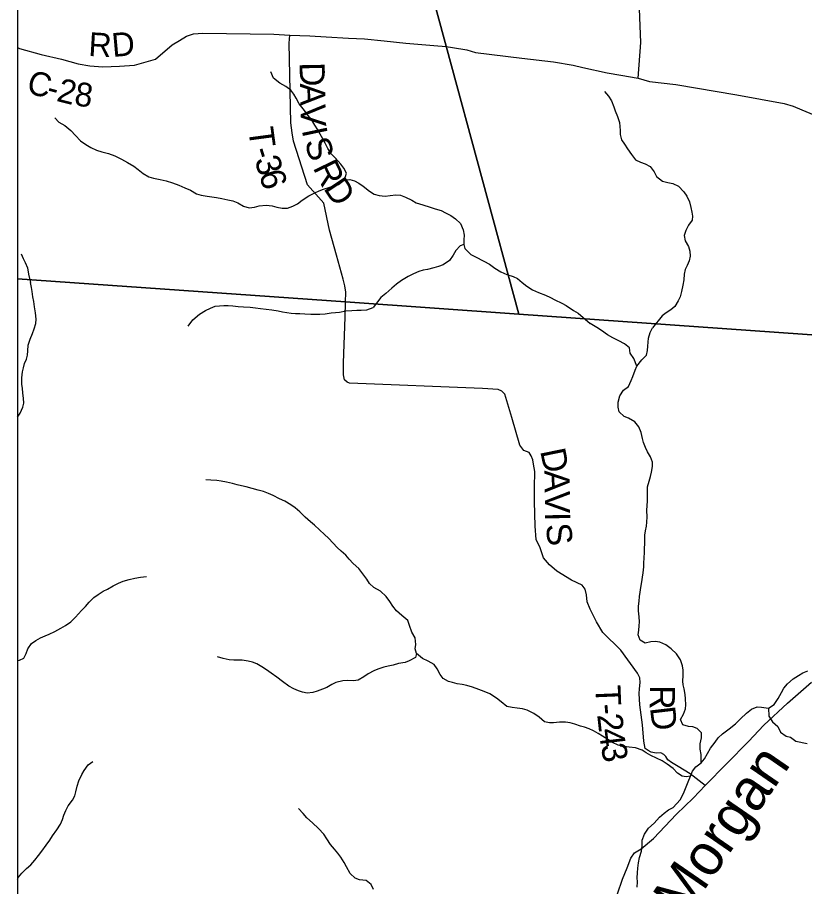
# Model space of a CAD drawing. Extents: x -139 to 835, y 0 to 440.
# Drawn here: x 67.6 to 127.4, y 290.4 to 356.4 of the extents above; entities that cross this region are included whole.
import ezdxf

# ---------------------------------------------------------------- set-up
doc = ezdxf.new("R2010")
doc.units = 0
for name, color, linetype in [('Default', 7, 'Continuous'), ('GM_X_County_Road', 7, 'Continuous'), ('GM_X_County_Road_Text', 7, 'Continuous'), ('GM_X_County_Text', 7, 'Continuous'), ('GM_X_Minor_River', 7, 'Continuous'), ('GM_X_Minor_River_Text', 7, 'Continuous'), ('GM_X_Township_Road', 7, 'Continuous'), ('GM_X_Township_Road_Text', 7, 'Continuous'), ('SH_Cut_Line', 7, 'Continuous')]:
    doc.layers.add(name, color=color, linetype=linetype)

msp = doc.modelspace()

# ---------------------------------------------------------------- linework, layer by layer
at = {"layer": 'Default'}
msp.add_lwpolyline([(122.213, 350.484), (122.213, 350.484), (122.213, 350.484), (122.213, 350.484)], close=True, dxfattribs=at)
at = {"layer": 'GM_X_County_Road'}
for points in [[(67.578, 354.075), (67.744, 354.001), (69.374, 353.566), (70.924, 353.205), (72.198, 352.834), (73.073, 352.682), (74.077, 352.622), (75.337, 352.662), (76.469, 352.753), (78.065, 353.205), (79.345, 354.278), (79.89, 354.624), (80.429, 354.959), (80.946, 355.122), (81.654, 355.177), (87.067, 355.109), (88.262, 355.036), (89.792, 354.973), (91.035, 354.9), (92.738, 354.8), (93.952, 354.741), (95.425, 354.596), (97.089, 354.415), (99.212, 354.251), (100.152, 354.161), (100.624, 354.086)], [(100.624, 354.086), (101.703, 353.916), (102.381, 353.715), (105.89, 353.277), (108.3, 352.994), (109.782, 352.747), (110.527, 352.58), (112.371, 352.161), (113.415, 351.988), (114.73, 351.757), (115.597, 351.513), (117.577, 351.268), (122.213, 350.484), (125.805, 349.823), (126.493, 349.639), (127.165, 349.341), (128.555, 348.774)], [(113.147, 289.815), (113.54, 290.92), (113.892, 291.773), (114.179, 292.518), (114.437, 292.913), (114.948, 293.234), (115.882, 294.02), (117.639, 295.859), (118.895, 297.076), (119.378, 297.567), (119.818, 298.043), (123.113, 301.386), (124.268, 302.604), (126.061, 304.297), (127.891, 305.87)]]:
    msp.add_lwpolyline(points, dxfattribs=at)
at = {"layer": 'GM_X_County_Text'}
for points in [[(87.298, 401.486), (67.578, 401.486), (67.578, 336.518), (92.493, 334.759), (105.67, 333.828), (100.145, 354.177), (90.116, 391.109)], [(205.139, 401.486), (87.298, 401.486), (90.116, 391.109), (100.145, 354.177), (105.67, 333.828), (158.444, 330.1), (160.688, 329.921), (171.559, 329.033), (172.321, 330.669), (184.767, 357.384), (185.383, 358.364), (185.729, 359.048), (185.902, 359.821), (186.018, 360.334), (186.292, 360.95), (186.616, 361.275), (187.014, 361.689), (203.078, 396.689), (203.294, 397.153), (203.246, 397.371), (203.278, 397.973), (203.623, 399.152)]]:
    msp.add_lwpolyline(points, close=True, dxfattribs=at)
msp.add_lwpolyline([(164.238, 274.594), (166.338, 293.196), (166.41, 293.836), (158.512, 319.627), (160.688, 329.921), (158.444, 330.1), (105.67, 333.828), (92.493, 334.759), (67.578, 336.518), (67.578, 185.387)], dxfattribs=at)
at = {"layer": 'GM_X_Minor_River'}
for points in [[(92.421, 344.046), (92.566, 344.538), (92.368, 344.926), (92.156, 345.23), (91.719, 345.705), (91.406, 346.01), (91.145, 346.423), (90.947, 346.81), (90.786, 347.15), (90.563, 347.514), (90.389, 347.829), (90.178, 348.181), (89.904, 348.606), (89.63, 348.959), (89.394, 349.311), (88.981, 349.798), (88.759, 350.234), (88.572, 350.538), (88.348, 350.842), (87.971, 351.123), (87.506, 351.382), (87.041, 351.761), (86.819, 352.245)], [(112.169, 350.733), (112.469, 350.38), (112.706, 350.028), (112.89, 349.592), (112.975, 349.289), (113.16, 348.853), (113.306, 348.381), (113.341, 348.08), (113.362, 347.778), (113.371, 347.476), (113.455, 347.066), (113.679, 346.75), (113.928, 346.397), (114.214, 345.948), (114.526, 345.547), (114.904, 345.374), (115.27, 345.249), (115.647, 345.04), (115.947, 344.639), (116.132, 344.287), (116.571, 343.933), (116.988, 343.844), (117.367, 343.755), (117.783, 343.557), (118.196, 343.131), (118.433, 342.803), (118.63, 342.354), (118.726, 341.931), (118.798, 341.581), (118.845, 341.267), (118.816, 340.966), (118.558, 340.583), (118.35, 340.176), (118.218, 339.803), (118.302, 339.405), (118.55, 338.968), (118.647, 338.617), (118.668, 338.243), (118.6, 337.882), (118.444, 337.535), (118.301, 337.223), (118.233, 336.862), (118.19, 336.44), (118.121, 336.031), (118.027, 335.562), (117.908, 335.154), (117.764, 334.842), (117.518, 334.411), (117.199, 334.173), (116.866, 333.936), (116.547, 333.71), (115.807, 332.785)], [(70.417, 348.751), (70.717, 348.41), (71.183, 348.164), (71.634, 347.773), (71.997, 347.395), (72.372, 347.005), (72.774, 346.724), (73.152, 346.502), (73.58, 346.293), (73.984, 346.168), (74.502, 346.029), (74.981, 345.855), (75.498, 345.608), (75.951, 345.362), (76.416, 345.068), (76.743, 344.823), (77.119, 344.517), (77.56, 344.271), (77.926, 344.171), (78.431, 344.069), (78.874, 343.955), (79.353, 343.805), (79.845, 343.631), (80.299, 343.433), (80.715, 343.248), (81.18, 342.965), (81.534, 342.865), (81.989, 342.788), (82.343, 342.735), (82.71, 342.695), (83.102, 342.63), (83.57, 342.529), (83.936, 342.452), (84.327, 342.291), (84.742, 342.033), (85.184, 341.92), (85.578, 341.964), (85.946, 342.068), (86.467, 342.123), (86.922, 342.069), (87.288, 341.969), (87.68, 341.88), (88.098, 341.876), (88.493, 342.028), (88.85, 342.217), (89.208, 342.502), (89.707, 342.822), (90.166, 343.058), (90.497, 343.199), (90.828, 343.316), (91.298, 343.467), (91.642, 343.572), (91.96, 343.677), (92.421, 344.046), (92.839, 344.065), (93.18, 343.953), (93.507, 343.792), (93.834, 343.548), (94.311, 343.181), (94.688, 342.959), (95.067, 342.847), (95.523, 342.805), (95.891, 342.837), (96.309, 342.893), (96.676, 342.865), (97.055, 342.728), (97.546, 342.494), (97.873, 342.297), (98.378, 342.147), (98.921, 341.948), (99.299, 341.835), (99.754, 341.697), (100.094, 341.537), (100.497, 341.327), (100.862, 341.082), (101.237, 340.728), (101.447, 340.232), (101.505, 339.845), (101.488, 339.472), (101.496, 339.134), (101.569, 338.82), (102.019, 338.369), (102.372, 338.196), (103.001, 337.852), (103.442, 337.618), (103.844, 337.324), (104.309, 337.041), (104.763, 336.844), (105.23, 336.694), (105.57, 336.533), (105.921, 336.228), (106.272, 335.947), (106.713, 335.689), (107.154, 335.491), (107.683, 335.268), (108.074, 335.107), (108.401, 334.922), (108.918, 334.663), (109.27, 334.479), (109.823, 334.123), (110.163, 333.902)], [(101.496, 339.134), (101.204, 339.029), (100.87, 338.671), (100.675, 338.312), (100.391, 337.905), (99.919, 337.585), (99.562, 337.444), (99.206, 337.352), (98.736, 337.236), (98.406, 337.168), (98.062, 337.075), (97.667, 336.887), (97.247, 336.686), (96.762, 336.402), (96.378, 336.105), (96.007, 335.82), (95.571, 335.415), (95.187, 335.094), (94.601, 334.333)], [(67.87, 338.412), (68.017, 338.061), (68.166, 337.746), (68.338, 337.346), (68.421, 336.863), (68.568, 336.233)], [(67.578, 326.019), (67.786, 326.304), (68.002, 326.763), (68.066, 327.065), (68.041, 327.463), (68.003, 327.838), (67.965, 328.2), (67.927, 328.502), (67.914, 329.009), (67.978, 329.456), (68.041, 329.758), (68.118, 330.096), (68.271, 330.411), (68.334, 330.713), (68.36, 331.051), (68.398, 331.473), (68.551, 331.932), (68.729, 332.355), (68.856, 332.718), (68.971, 333.128), (68.996, 333.454), (68.958, 333.925), (68.882, 334.384), (68.819, 334.795), (68.756, 335.145), (68.692, 335.544), (68.642, 335.846), (68.568, 336.233)], [(80.537, 332.922), (80.906, 333.393), (81.415, 333.84), (81.872, 334.118), (82.241, 334.299), (82.597, 334.432), (82.927, 334.468), (83.27, 334.492), (83.588, 334.492), (83.944, 334.456), (84.338, 334.42), (84.758, 334.395), (85.253, 334.371), (85.673, 334.323), (86.054, 334.262), (86.461, 334.202), (86.893, 334.154), (87.376, 334.081), (87.719, 334.021), (88.037, 333.948), (88.367, 333.9), (88.71, 333.888), (89.041, 333.876), (89.422, 333.851), (89.854, 333.839), (90.553, 333.839), (90.96, 333.863), (91.405, 333.924), (91.735, 333.96), (92.053, 333.996), (92.536, 334.081), (92.968, 334.117), (93.35, 334.129), (93.68, 334.129), (94.125, 334.165), (94.601, 334.333)], [(110.163, 333.902), (111.071, 333.131)], [(114.637, 329.876), (114.396, 330.467), (114.116, 330.878), (114.066, 331.265), (113.685, 331.591), (113.253, 331.82), (112.808, 332.038), (112.389, 332.255), (111.931, 332.581), (111.575, 332.811), (111.071, 333.131)], [(119.508, 299.745), (119.516, 300.377), (119.44, 300.788), (119.44, 301.198), (119.542, 301.657), (119.542, 302.032), (119.199, 302.37), (118.881, 302.479), (118.551, 302.515), (118.119, 302.648), (117.954, 303.035), (118.17, 303.457), (118.31, 303.856), (118.336, 304.17), (118.31, 304.605), (118.285, 304.955), (118.209, 305.366), (118.146, 305.668), (118.12, 305.97), (118.146, 306.381), (118.146, 306.792), (118.096, 307.13), (117.931, 307.577), (117.651, 308.024), (117.232, 308.422), (116.838, 308.712), (116.381, 308.918), (116.025, 308.966), (115.694, 308.942), (115.262, 308.845), (114.881, 309.063), (114.729, 309.486), (114.78, 309.824), (114.793, 310.162), (114.818, 310.476), (114.793, 310.85), (114.742, 311.31), (114.755, 311.66), (114.793, 312.034), (114.819, 312.385), (114.87, 312.711), (114.934, 313.061), (115.01, 313.508), (115.061, 313.846), (115.1, 314.197), (115.151, 314.631), (115.164, 314.933), (115.189, 315.32), (115.202, 315.719), (115.215, 316.045), (115.228, 316.419), (115.228, 316.745), (115.241, 317.059), (115.292, 317.386), (115.356, 317.724), (115.394, 318.026), (115.407, 318.436), (115.382, 318.92), (115.42, 319.306), (115.445, 319.62), (115.446, 319.958), (115.433, 320.405), (115.446, 320.707), (115.561, 321.154), (115.662, 321.492), (115.739, 321.843), (115.815, 322.253), (115.828, 322.58), (115.663, 322.99), (115.435, 323.389), (115.282, 323.715), (115.143, 324.089), (115.067, 324.392), (114.952, 324.851), (114.787, 325.273), (114.47, 325.66), (113.987, 325.926), (113.657, 326.071), (113.288, 326.421), (113.212, 326.759), (113.212, 327.158), (113.34, 327.641), (113.619, 328.052), (114.001, 328.341), (114.204, 328.8), (114.319, 329.102), (114.497, 329.574), (114.637, 329.876), (114.993, 330.359), (115.362, 330.709), (115.438, 331.071), (115.464, 331.397), (115.49, 331.711), (115.515, 332.013), (115.63, 332.448), (115.807, 332.785)], [(82.718, 321.193), (82.273, 321.229), (81.892, 321.241)], [(118.69, 298.737), (118.383, 298.698), (118.066, 298.734), (117.71, 298.976), (117.392, 299.326), (116.935, 299.652), (116.541, 299.918), (116.109, 300.099), (115.69, 300.305), (115.347, 300.51), (115.029, 300.715), (114.533, 300.885), (114.051, 300.957), (113.644, 301.005), (113.212, 301.102), (112.767, 301.308), (112.424, 301.537), (112.017, 301.791), (111.7, 301.972), (111.344, 302.177), (111.001, 302.334), (110.658, 302.467), (110.34, 302.552), (109.921, 302.685), (109.565, 302.781), (109.209, 302.842), (108.764, 302.842), (108.307, 302.794), (107.989, 302.794), (107.62, 302.878), (107.214, 303.229), (106.807, 303.506), (106.286, 303.748), (105.943, 303.857), (105.536, 303.917), (105.155, 303.954), (104.748, 304.038), (104.329, 304.376), (103.973, 304.666), (103.465, 304.992), (103.033, 305.174), (102.627, 305.319), (102.156, 305.512), (101.724, 305.633), (101.356, 305.693), (100.987, 305.766), (100.631, 305.85), (100.314, 305.935), (99.907, 306.164), (99.678, 306.466), (99.463, 306.901), (99.221, 307.215), (98.777, 307.481), (98.357, 307.687), (97.9, 308.049), (97.798, 308.424), (97.849, 308.75), (97.786, 309.257), (97.532, 309.68), (97.367, 310.187), (97.227, 310.562), (96.783, 310.936), (96.376, 311.299), (96.084, 311.649), (95.868, 312.011), (95.589, 312.386), (95.157, 312.785), (94.649, 313.075), (94.318, 313.377), (94.115, 313.715), (93.747, 314.21), (93.505, 314.512), (93.073, 314.887), (92.781, 315.213), (92.515, 315.539), (92.172, 315.829), (91.854, 316.119), (91.562, 316.445), (91.206, 316.807), (90.901, 317.109), (90.52, 317.448), (90.152, 317.798), (89.834, 318.064), (89.427, 318.426), (89.034, 318.825), (88.665, 319.127), (88.335, 319.344), (87.89, 319.622), (87.496, 319.816), (87.013, 320.057), (86.658, 320.214), (86.276, 320.359), (85.857, 320.468), (85.399, 320.589), (84.955, 320.722), (84.599, 320.806), (84.281, 320.879), (83.925, 320.975), (83.455, 321.072), (83.048, 321.145), (82.718, 321.193)], [(67.578, 307.54), (67.739, 307.544), (68.057, 307.701), (68.248, 308.052), (68.362, 308.402), (68.642, 308.813), (68.985, 309.054), (69.329, 309.247), (69.685, 309.404), (70.002, 309.537), (70.422, 309.73), (70.867, 309.972), (71.223, 310.177), (71.63, 310.455), (71.998, 310.817), (72.456, 311.325), (72.761, 311.639), (73.041, 311.965), (73.372, 312.303), (73.715, 312.545), (74.097, 312.798), (74.427, 312.955), (74.859, 313.197), (75.266, 313.414), (75.609, 313.559), (76.067, 313.68), (76.486, 313.777), (76.931, 313.849), (77.376, 313.897)], [(97.9, 308.049), (97.811, 307.747), (97.34, 307.493), (97.023, 307.385), (96.527, 307.288), (96.107, 307.179), (95.739, 307.095), (95.408, 307.01), (94.963, 306.878), (94.645, 306.745), (94.213, 306.515), (93.895, 306.286), (93.45, 306.032), (93.107, 305.984), (92.688, 306.008), (92.294, 305.972), (91.773, 305.851), (91.455, 305.694), (91.086, 305.489), (90.756, 305.356), (90.336, 305.187), (90.018, 305.09), (89.586, 305.054), (89.243, 305.126), (88.925, 305.223), (88.569, 305.368), (88.201, 305.585), (87.718, 305.924), (87.273, 306.262), (86.841, 306.576), (86.486, 306.83), (86.155, 307.035), (85.762, 307.265), (85.444, 307.398), (85.113, 307.47), (84.656, 307.543), (84.338, 307.555), (84.008, 307.543), (83.652, 307.579), (83.207, 307.676), (82.775, 307.809)], [(125.048, 304.197), (125.367, 304.654), (125.624, 305.086), (125.778, 305.423), (126.071, 305.747), (126.505, 306.142), (126.899, 306.393), (127.242, 306.583), (127.624, 306.738)], [(114.658, 290.309), (114.673, 290.707), (114.663, 291.033), (114.665, 291.407), (114.705, 291.744), (114.759, 292.166), (114.837, 292.575), (114.98, 293.057), (115.02, 293.454), (115.023, 293.888), (115.203, 294.333), (115.523, 294.802), (115.931, 295.173), (116.352, 295.617), (116.709, 295.94), (117.04, 296.191), (117.396, 296.358), (117.919, 296.946), (118.163, 297.438), (118.33, 297.811), (118.536, 298.304), (118.69, 298.737), (118.845, 299.134), (119.1, 299.458), (119.508, 299.745), (119.776, 300.057), (119.981, 300.466), (120.212, 300.862), (120.569, 301.318), (120.812, 301.643), (121.144, 301.954), (121.64, 302.325), (122.124, 302.708), (122.507, 303.103), (122.966, 303.535), (123.335, 303.834), (123.754, 304), (124.096, 303.974), (124.615, 303.899), (125.048, 304.197)], [(124.615, 303.899), (124.652, 303.288), (124.919, 302.877), (125.338, 302.527), (125.541, 302.08), (125.973, 301.778), (126.291, 301.717), (126.71, 301.391), (127.574, 301.222)], [(67.578, 290.925), (67.667, 291.078), (67.922, 291.38), (68.265, 291.718), (68.596, 292.02), (68.913, 292.359), (69.193, 292.709), (69.435, 293.047), (69.766, 293.494), (70.033, 293.893), (70.249, 294.219), (70.58, 294.666), (70.847, 295.089), (70.999, 295.451), (71.114, 295.789), (71.254, 296.128), (71.445, 296.478), (71.776, 296.913), (71.941, 297.239), (72.017, 297.553), (72.107, 297.988), (72.234, 298.399), (72.476, 298.858), (72.654, 299.184), (72.959, 299.595), (73.302, 299.848)], [(94.637, 290.146), (94.459, 290.508), (94.065, 290.81), (93.557, 290.871), (93.239, 291.004), (92.858, 291.354), (92.579, 291.849), (92.388, 292.188), (92.147, 292.586), (91.906, 292.888), (91.652, 293.19), (91.372, 293.553), (91.093, 293.988), (90.852, 294.338), (90.458, 294.773), (89.988, 295.196), (89.569, 295.583), (89.289, 295.897), (88.933, 296.283)]]:
    msp.add_lwpolyline(points, dxfattribs=at)
at = {"layer": 'GM_X_Township_Road'}
for points in [[(114.73, 351.757), (114.92, 354.47), (114.77, 358.303), (114.741, 359.581)], [(92.501, 334.742), (92.517, 335.492), (92.446, 335.994), (92.327, 336.503), (91.806, 338.309), (91.279, 340.221), (90.859, 342.261), (89.6, 343.655), (88.559, 346.975), (88.444, 347.611), (88.348, 348.373), (88.224, 354.419), (88.262, 355.036)], [(119.818, 298.043), (118.688, 298.912), (117.756, 299.476), (117.253, 299.783), (116.989, 299.979), (116.84, 300.234), (116.689, 300.392), (116.437, 300.515), (116.082, 300.483), (115.703, 300.559), (115.489, 300.682), (115.263, 300.841), (115.168, 301.41), (115.055, 302.653), (114.844, 304.163), (114.803, 305.02), (114.82, 305.369), (114.876, 305.851), (114.842, 306.214), (114.681, 306.565), (113.408, 308.303), (112.055, 309.657), (111.57, 310.47), (111.086, 311.428), (110.865, 311.973), (110.795, 312.516), (110.698, 312.951), (110.486, 313.255), (109.654, 313.638), (108.546, 314.301), (107.982, 314.79), (107.532, 315.325), (107.274, 316.076), (106.99, 316.73), (106.912, 317.72), (106.858, 319.602), (106.857, 320.675), (106.871, 321.881), (106.776, 322.437), (106.716, 322.763), (106.611, 323.082), (106.446, 323.323), (106.039, 323.48), (105.733, 323.89), (105.123, 325.978), (104.601, 327.764), (104.372, 327.981), (104.089, 328.103), (102.892, 328.185), (92.805, 328.597), (92.631, 328.679), (92.423, 328.844), (92.336, 329.223), (92.354, 330.129), (92.464, 333.606), (92.501, 334.742)]]:
    msp.add_lwpolyline(points, dxfattribs=at)
at = {"layer": 'SH_Cut_Line'}
for points in [[(295.458, 319.381), (295.458, 401.486), (67.578, 401.486), (67.578, 336.518), (92.493, 334.759), (105.67, 333.828), (158.444, 330.1), (160.688, 329.921), (171.559, 329.033), (177.155, 328.576), (194.287, 327.176), (207.436, 326.102), (228.151, 324.569), (267.909, 321.538)], [(67.578, 336.518), (67.578, 185.387), (295.458, 185.387), (295.458, 319.381), (267.909, 321.538), (228.151, 324.569), (207.436, 326.102), (194.287, 327.176), (177.155, 328.576), (171.559, 329.033), (160.688, 329.921), (158.444, 330.1), (105.67, 333.828), (92.493, 334.759)]]:
    msp.add_lwpolyline(points, close=True, dxfattribs=at)

# ---------------------------------------------------------------- texts
at = {"layer": 'GM_X_County_Road_Text'}
for s, height, rotation, p in [('R', 1.806, 356.64413, (72.944, 353.45)), ('D', 1.807, 5.04714, (74.821, 353.363)), ('C', 1.818, 344.72727, (68.19, 350.665)), ('2', 1.817, 345.69583, (70.48, 350.042)), ('8', 1.809, 351.80509, (71.841, 349.708)), ('-', 1.818, 344.88985, (69.699, 350.253))]:
    msp.add_text(s, height=height, rotation=rotation, dxfattribs=at).set_placement(p)
at = {"layer": 'GM_X_Minor_River_Text'}
msp.add_text('Morgan', height=3.1495, rotation=55.43883, dxfattribs=at).set_placement((118.266, 287.899))
at = {"layer": 'GM_X_Township_Road_Text'}
for s, height, rotation, p in [('D', 1.904, 271.05256, (89.013, 352.95)), ('A', 1.904, 271.06428, (89.042, 351.361)), ('V', 1.904, 272.0074, (89.072, 349.742)), ('T', 1.904, 277.63052, (85.106, 347.918)), ('I', 1.903, 281.94908, (89.167, 347.831)), ('S', 1.902, 287.21595, (89.365, 346.936)), ('-', 1.902, 287.08435, (85.352, 346.276)), ('3', 1.902, 287.08012, (85.571, 345.564)), ('R', 1.897, 295.77943, (89.997, 344.968)), ('6', 1.902, 287.30171, (85.901, 344.489)), ('D', 1.891, 303.69626, (90.781, 343.387)), ('D', 1.903, 281.5987, (107.277, 323.452)), ('A', 1.904, 271.58665, (107.588, 321.971)), ('V', 1.904, 270.76447, (107.632, 320.389)), ('I', 1.904, 271.09052, (107.654, 318.79)), ('S', 1.904, 277.98101, (107.685, 317.824)), ('T', 1.904, 272.35954, (111.476, 305.628)), ('R', 1.904, 269.72424, (115.617, 305.649)), ('-', 1.904, 275.36988, (111.538, 304.18)), ('D', 1.904, 276.68842, (115.622, 303.943)), ('2', 1.904, 276.31069, (111.61, 303.411)), ('4', 1.904, 276.81832, (111.734, 302.288)), ('3', 1.903, 280.09412, (111.882, 301.077))]:
    msp.add_text(s, height=height, rotation=rotation, dxfattribs=at).set_placement(p)

doc.saveas('drawing.dxf')
